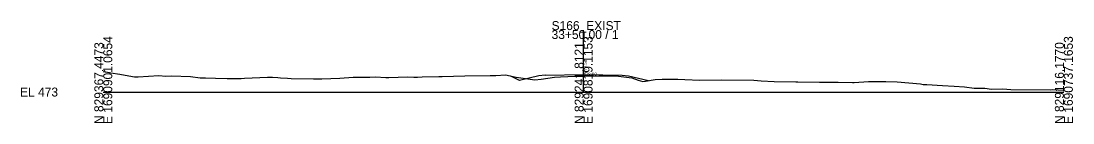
# Model space of a CAD drawing. Extents: x 1621104 to 1621433, y 1192880 to 1199414.
# Drawn here: x 1621104.2 to 1621432.7, y 1198879.5 to 1198911.5 of the extents above; entities that cross this region are included whole.
import ezdxf

# ---------------------------------------------------------------- set-up
doc = ezdxf.new("R2010")
doc.units = 0
for name, color, linetype in [('RD_GPK_XS_Cell', 7, 'Continuous'), ('RD_XS_EarthShd', 7, 'Continuous'), ('RD_XS_ExGround', 7, 'Continuous'), ('RD_XS_Pave', 7, 'Continuous'), ('RD_XS_TieSlope', 7, 'Continuous'), ('RD_XS_TX_Elev_EX', 7, 'Continuous'), ('RD_XS_TX_Elev_PR', 7, 'Continuous')]:
    doc.layers.add(name, color=color, linetype=linetype)

msp = doc.modelspace()

# ---------------------------------------------------------------- linework, layer by layer
at = {"layer": 'RD_GPK_XS_Cell'}
for p, q in [((1621279.86, 1198889.24), (1621279.86, 1198908.65)), ((1621129.86, 1198889.24), (1621279.86, 1198889.24)), ((1621279.86, 1198889.24), (1621429.86, 1198889.24))]:
    msp.add_line(p, q, dxfattribs=at)
at = {"layer": 'RD_XS_EarthShd'}
for p, q in [((1621267.86, 1198894.53), (1621265.86, 1198894.37)), ((1621291.86, 1198894.53), (1621293.86, 1198894.37))]:
    msp.add_line(p, q, dxfattribs=at)
at = {"layer": 'RD_XS_ExGround'}
msp.add_lwpolyline([(1621129.86, 1198895.71), (1621131.83, 1198895.39), (1621132.18, 1198895.31), (1621135.04, 1198894.8), (1621139, 1198894.09), (1621139.59, 1198893.99), (1621140.78, 1198893.97), (1621147.17, 1198894.4), (1621149.41, 1198894.21), (1621151.18, 1198894.3), (1621157.1, 1198894.16), (1621160.07, 1198893.73), (1621161.74, 1198893.65), (1621164.88, 1198893.6), (1621168.53, 1198893.46), (1621171.81, 1198893.5), (1621172.91, 1198893.53), (1621173.91, 1198893.6), (1621181.17, 1198893.86), (1621182.69, 1198893.88), (1621184.4, 1198893.78), (1621185.18, 1198893.71), (1621187.39, 1198893.56), (1621188.55, 1198893.52), (1621195.54, 1198893.39), (1621196.98, 1198893.34), (1621198.07, 1198893.38), (1621203.75, 1198893.58), (1621207.91, 1198893.87), (1621209.66, 1198893.92), (1621210.29, 1198893.89), (1621213.05, 1198893.93), (1621214.84, 1198893.98), (1621218.05, 1198893.81), (1621219, 1198893.83), (1621224.89, 1198894.02), (1621226.84, 1198893.89), (1621227.98, 1198893.95), (1621229.44, 1198893.99), (1621234.6, 1198894.06), (1621235.71, 1198894.15), (1621242.76, 1198894.36), (1621250.68, 1198894.39), (1621252.47, 1198894.41), (1621255.45, 1198894.58), (1621258.8, 1198893.9), (1621264.58, 1198893.02), (1621266.57, 1198893.32), (1621270.77, 1198893.9), (1621272.6, 1198894.02), (1621277.24, 1198894.18), (1621278.83, 1198894.25), (1621279.99, 1198894.23), (1621284.61, 1198894.27), (1621286.93, 1198894.35), (1621289.35, 1198894.36), (1621290.79, 1198894.22), (1621294.9, 1198893.65), (1621296.93, 1198892.95), (1621298.41, 1198892.54), (1621299.22, 1198892.65), (1621302.24, 1198893.22), (1621304.39, 1198893.29), (1621305.73, 1198893.26), (1621309.29, 1198893.28), (1621311.52, 1198893.13), (1621316.15, 1198892.98), (1621323.01, 1198893.1), (1621333.07, 1198892.92), (1621335.34, 1198892.77), (1621339.4, 1198892.58), (1621346.15, 1198892.41), (1621346.75, 1198892.44), (1621353.56, 1198892.37), (1621354.86, 1198892.34), (1621359.38, 1198892.29), (1621363.87, 1198892.2), (1621364.39, 1198892.21), (1621368.89, 1198892.57), (1621374.23, 1198892.52), (1621377.81, 1198892.47), (1621385.08, 1198891.78), (1621385.88, 1198891.61), (1621387.05, 1198891.61), (1621391.92, 1198891.27), (1621395.56, 1198891.11), (1621398.87, 1198890.91), (1621401.86, 1198890.42), (1621405.22, 1198890.45), (1621407.28, 1198890.19), (1621410.56, 1198890.2), (1621412.08, 1198890.1), (1621413.32, 1198890), (1621425.55, 1198889.94), (1621426.19, 1198889.99), (1621428.07, 1198889.91), (1621429.86, 1198889.8)], dxfattribs=at)
at = {"layer": 'RD_XS_Pave'}
for p, q in [((1621267.86, 1198894.53), (1621279.86, 1198894.77)), ((1621279.86, 1198894.77), (1621291.86, 1198894.53))]:
    msp.add_line(p, q, dxfattribs=at)
at = {"layer": 'RD_XS_TieSlope'}
for p, q in [((1621265.86, 1198894.37), (1621259.86, 1198892.87)), ((1621293.86, 1198894.37), (1621300.1, 1198892.81)), ((1621259.86, 1198892.87), (1621257.12, 1198894.24))]:
    msp.add_line(p, q, dxfattribs=at)

# ---------------------------------------------------------------- texts
at = {"layer": 'RD_GPK_XS_Cell'}
for s, p in [('S166_EXIST', (1621269.86, 1198908.65)), ('33+50.00 / 1', (1621269.86, 1198905.85)), ('EL 473', (1621103.86, 1198887.84))]:
    msp.add_text(s, height=2.8, dxfattribs=at).set_placement(p)
for s, p in [('N 829367.4473', (1621129.86, 1198879.24)), ('E 1690901.0654', (1621132.66, 1198879.24)), ('N 829241.8121', (1621279.86, 1198879.24)), ('E 1690819.1153', (1621282.66, 1198879.24)), ('N 829116.1770', (1621429.86, 1198879.24)), ('E 1690737.1653', (1621432.66, 1198879.24))]:
    msp.add_text(s, height=2.8, rotation=90, dxfattribs=at).set_placement(p)
at = {"layer": 'RD_XS_TX_Elev_EX'}
msp.add_text('478.00', height=1, dxfattribs=at).set_placement((1621279.76, 1198894.33))
at = {"layer": 'RD_XS_TX_Elev_PR'}
msp.add_text(' 478.53', height=1, rotation=90, dxfattribs=at).set_placement((1621280.86, 1198894.77))

doc.saveas('drawing.dxf')
